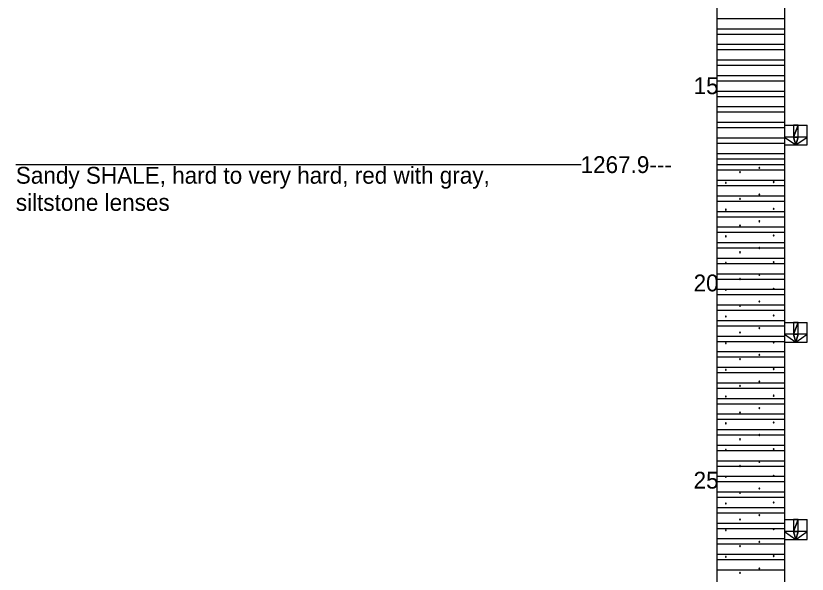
# Model space of a CAD drawing. Extents: x 7 to 126, y 24 to 56.
# Drawn here: x 27.98 to 33.81, y 42.13 to 46.24 of the extents above; entities that cross this region are included whole.
import ezdxf

# ---------------------------------------------------------------- set-up
doc = ezdxf.new("R2010")
doc.units = 0

msp = doc.modelspace()

# ---------------------------------------------------------------- linework, layer by layer
for points in [[(33.1403, 50.0867), (33.1403, 38.1681)], [(33.6403, 50.0867), (33.6403, 38.1681)], [(33.1403, 46.2217), (33.6403, 46.2217)], [(33.1403, 46.1463), (33.6403, 46.1463)], [(33.1403, 46.1069), (33.6403, 46.1069)], [(33.1403, 46.0315), (33.6403, 46.0315)], [(33.1403, 45.9921), (33.6403, 45.9921)], [(33.1403, 45.9166), (33.6403, 45.9166)], [(33.1403, 45.8773), (33.6403, 45.8773)], [(33.1403, 45.8018), (33.6403, 45.8018)], [(33.1403, 45.7624), (33.6403, 45.7624)], [(33.1403, 45.687), (33.6403, 45.687)], [(33.1403, 45.6476), (33.6403, 45.6476)], [(33.1403, 45.5721), (33.6403, 45.5721)], [(33.1403, 45.5328), (33.6403, 45.5328)], [(33.1403, 45.4573), (33.6403, 45.4573)], [(33.6403, 45.4356), (33.807, 45.4356)], [(33.807, 45.2902), (33.807, 45.4356)], [(33.1403, 45.4179), (33.6403, 45.4179)], [(33.1403, 45.3425), (33.6403, 45.3425)], [(33.1403, 45.3031), (33.6403, 45.3031)], [(33.6403, 45.2902), (33.807, 45.2902)], [(33.1403, 45.2277), (33.6403, 45.2277)], [(27.9751, 45.1449), (32.1417, 45.1449)], [(33.1403, 45.1883), (33.6403, 45.1883)], [(33.1403, 45.1449), (33.6403, 45.1449)], [(33.1403, 45.1449), (33.6403, 45.1449)], [(33.1403, 45.1055), (33.6403, 45.1055)], [(33.3154, 45.089), (33.3137, 45.0919), (33.3104, 45.0919), (33.3088, 45.0891), (33.3104, 45.0862), (33.3137, 45.0862), (33.3154, 45.089)], [(33.4579, 45.1209), (33.4563, 45.1237), (33.453, 45.1237), (33.4514, 45.1209), (33.453, 45.1181), (33.4563, 45.1181), (33.4579, 45.1209)], [(33.1403, 45.03), (33.6403, 45.03)], [(33.1403, 44.9907), (33.6403, 44.9907)], [(33.2107, 45.0101), (33.2091, 45.0129), (33.2058, 45.0129), (33.2041, 45.0101), (33.2058, 45.0072), (33.2091, 45.0072), (33.2107, 45.0101)], [(33.5635, 45.0166), (33.5618, 45.0195), (33.5585, 45.0195), (33.5569, 45.0166), (33.5585, 45.0138), (33.5618, 45.0138), (33.5635, 45.0166)], [(33.1403, 44.9152), (33.6403, 44.9152)], [(33.4579, 44.9241), (33.4563, 44.9269), (33.453, 44.9269), (33.4514, 44.9241), (33.453, 44.9212), (33.4563, 44.9212), (33.4579, 44.9241)], [(33.1403, 44.8758), (33.6403, 44.8758)], [(33.3154, 44.8922), (33.3137, 44.8951), (33.3104, 44.8951), (33.3088, 44.8922), (33.3104, 44.8894), (33.3137, 44.8894), (33.3154, 44.8922)], [(33.1403, 44.8004), (33.6403, 44.8004)], [(33.2107, 44.8132), (33.2091, 44.8161), (33.2058, 44.8161), (33.2041, 44.8132), (33.2058, 44.8104), (33.2091, 44.8104), (33.2107, 44.8132)], [(33.5635, 44.8197), (33.5618, 44.8226), (33.5585, 44.8226), (33.5569, 44.8197), (33.5585, 44.8169), (33.5618, 44.8169), (33.5635, 44.8197)], [(33.1403, 44.761), (33.6403, 44.761)], [(33.1403, 44.6856), (33.6403, 44.6856)], [(33.3154, 44.6953), (33.3137, 44.6982), (33.3104, 44.6982), (33.3088, 44.6954), (33.3104, 44.6925), (33.3137, 44.6925), (33.3154, 44.6953)], [(33.4579, 44.7272), (33.4563, 44.73), (33.453, 44.73), (33.4514, 44.7272), (33.453, 44.7244), (33.4563, 44.7244), (33.4579, 44.7272)], [(33.1403, 44.6462), (33.6403, 44.6462)], [(33.2107, 44.6164), (33.2091, 44.6192), (33.2058, 44.6192), (33.2041, 44.6164), (33.2058, 44.6135), (33.2091, 44.6135), (33.2107, 44.6164)], [(33.5635, 44.6229), (33.5618, 44.6258), (33.5585, 44.6258), (33.5569, 44.6229), (33.5585, 44.6201), (33.5618, 44.6201), (33.5635, 44.6229)], [(33.1403, 44.5707), (33.6403, 44.5707)], [(33.1403, 44.5314), (33.6403, 44.5314)], [(33.3154, 44.4985), (33.3137, 44.5014), (33.3104, 44.5014), (33.3088, 44.4985), (33.3104, 44.4957), (33.3137, 44.4957), (33.3154, 44.4985)], [(33.4579, 44.5304), (33.4563, 44.5332), (33.453, 44.5332), (33.4514, 44.5304), (33.453, 44.5275), (33.4563, 44.5275), (33.4579, 44.5304)], [(33.1403, 44.4559), (33.6403, 44.4559)], [(33.1403, 44.4165), (33.6403, 44.4165)], [(33.2107, 44.4195), (33.2091, 44.4224), (33.2058, 44.4224), (33.2041, 44.4195), (33.2058, 44.4167), (33.2091, 44.4167), (33.2107, 44.4195)], [(33.5635, 44.426), (33.5618, 44.4289), (33.5585, 44.4289), (33.5569, 44.426), (33.5585, 44.4232), (33.5618, 44.4232), (33.5635, 44.426)], [(33.1403, 44.3411), (33.6403, 44.3411)], [(33.4579, 44.3335), (33.4563, 44.3363), (33.453, 44.3363), (33.4514, 44.3335), (33.453, 44.3307), (33.4563, 44.3307), (33.4579, 44.3335)], [(33.1403, 44.3017), (33.6403, 44.3017)], [(33.3154, 44.3016), (33.3137, 44.3045), (33.3104, 44.3045), (33.3088, 44.3017), (33.3104, 44.2988), (33.3137, 44.2988), (33.3154, 44.3016)], [(33.1403, 44.2262), (33.6403, 44.2262)], [(33.2107, 44.2227), (33.2091, 44.2255), (33.2058, 44.2255), (33.2041, 44.2227), (33.2058, 44.2198), (33.2091, 44.2198), (33.2107, 44.2227)], [(33.5635, 44.2292), (33.5618, 44.2321), (33.5585, 44.2321), (33.5569, 44.2292), (33.5585, 44.2264), (33.5618, 44.2264), (33.5635, 44.2292)], [(33.1403, 44.1869), (33.6403, 44.1869)], [(33.1403, 44.1114), (33.6403, 44.1114)], [(33.3154, 44.1048), (33.3137, 44.1077), (33.3104, 44.1077), (33.3088, 44.1048), (33.3104, 44.102), (33.3137, 44.102), (33.3154, 44.1048)], [(33.4579, 44.1367), (33.4563, 44.1395), (33.453, 44.1395), (33.4514, 44.1367), (33.453, 44.1338), (33.4563, 44.1338), (33.4579, 44.1367)], [(33.1403, 44.072), (33.6403, 44.072)], [(33.5635, 44.0323), (33.5618, 44.0352), (33.5585, 44.0352), (33.5569, 44.0323), (33.5585, 44.0295), (33.5618, 44.0295), (33.5635, 44.0323)], [(33.1403, 43.9966), (33.6403, 43.9966)], [(33.2107, 44.0258), (33.2091, 44.0287), (33.2058, 44.0287), (33.2041, 44.0258), (33.2058, 44.023), (33.2091, 44.023), (33.2107, 44.0258)], [(33.6403, 43.9821), (33.807, 43.9821)], [(33.807, 43.8367), (33.807, 43.9821)], [(33.1403, 43.9572), (33.6403, 43.9572)], [(33.4579, 43.9398), (33.4563, 43.9426), (33.453, 43.9426), (33.4514, 43.9398), (33.453, 43.937), (33.4563, 43.937), (33.4579, 43.9398)], [(33.1403, 43.8817), (33.6403, 43.8817)], [(33.3154, 43.9079), (33.3137, 43.9108), (33.3104, 43.9108), (33.3088, 43.908), (33.3104, 43.9051), (33.3137, 43.9051), (33.3154, 43.9079)], [(33.1403, 43.8424), (33.6403, 43.8424)], [(33.2107, 43.829), (33.2091, 43.8318), (33.2058, 43.8318), (33.2041, 43.829), (33.2058, 43.8261), (33.2091, 43.8261), (33.2107, 43.829)], [(33.5635, 43.8355), (33.5618, 43.8384), (33.5585, 43.8384), (33.5569, 43.8355), (33.5585, 43.8327), (33.5618, 43.8327), (33.5635, 43.8355)], [(33.6403, 43.8367), (33.807, 43.8367)], [(33.1403, 43.7669), (33.6403, 43.7669)], [(33.4579, 43.743), (33.4563, 43.7458), (33.453, 43.7458), (33.4514, 43.743), (33.453, 43.7401), (33.4563, 43.7401), (33.4579, 43.743)], [(33.1403, 43.7275), (33.6403, 43.7275)], [(33.3154, 43.7111), (33.3137, 43.714), (33.3104, 43.714), (33.3088, 43.7111), (33.3104, 43.7083), (33.3137, 43.7083), (33.3154, 43.7111)], [(33.1403, 43.6521), (33.6403, 43.6521)], [(33.2107, 43.6321), (33.2091, 43.635), (33.2058, 43.635), (33.2041, 43.6321), (33.2058, 43.6293), (33.2091, 43.6293), (33.2107, 43.6321)], [(33.5635, 43.6386), (33.5618, 43.6415), (33.5585, 43.6415), (33.5569, 43.6386), (33.5585, 43.6358), (33.5618, 43.6358), (33.5635, 43.6386)], [(33.1403, 43.6127), (33.6403, 43.6127)], [(33.1403, 43.5373), (33.6403, 43.5373)], [(33.3154, 43.5142), (33.3137, 43.5171), (33.3104, 43.5171), (33.3088, 43.5143), (33.3104, 43.5114), (33.3137, 43.5114), (33.3154, 43.5142)], [(33.4579, 43.5461), (33.4563, 43.5489), (33.453, 43.5489), (33.4514, 43.5461), (33.453, 43.5433), (33.4563, 43.5433), (33.4579, 43.5461)], [(33.1403, 43.4979), (33.6403, 43.4979)], [(33.1403, 43.4224), (33.6403, 43.4224)], [(33.2107, 43.4353), (33.2091, 43.4381), (33.2058, 43.4381), (33.2041, 43.4353), (33.2058, 43.4324), (33.2091, 43.4324), (33.2107, 43.4353)], [(33.5635, 43.4418), (33.5618, 43.4447), (33.5585, 43.4447), (33.5569, 43.4418), (33.5585, 43.439), (33.5618, 43.439), (33.5635, 43.4418)], [(33.1403, 43.3831), (33.6403, 43.3831)], [(33.4579, 43.3493), (33.4563, 43.3521), (33.453, 43.3521), (33.4514, 43.3493), (33.453, 43.3464), (33.4563, 43.3464), (33.4579, 43.3493)], [(33.1403, 43.3076), (33.6403, 43.3076)], [(33.3154, 43.3174), (33.3137, 43.3203), (33.3104, 43.3203), (33.3088, 43.3174), (33.3104, 43.3146), (33.3137, 43.3146), (33.3154, 43.3174)], [(33.1403, 43.2682), (33.6403, 43.2682)], [(33.2107, 43.2384), (33.2091, 43.2413), (33.2058, 43.2413), (33.2041, 43.2384), (33.2058, 43.2356), (33.2091, 43.2356), (33.2107, 43.2384)], [(33.5635, 43.2449), (33.5618, 43.2478), (33.5585, 43.2478), (33.5569, 43.2449), (33.5585, 43.2421), (33.5618, 43.2421), (33.5635, 43.2449)], [(33.1403, 43.1928), (33.6403, 43.1928)], [(33.1403, 43.1534), (33.6403, 43.1534)], [(33.3154, 43.1205), (33.3137, 43.1234), (33.3104, 43.1234), (33.3088, 43.1206), (33.3104, 43.1177), (33.3137, 43.1177), (33.3154, 43.1205)], [(33.4579, 43.1524), (33.4563, 43.1552), (33.453, 43.1552), (33.4514, 43.1524), (33.453, 43.1496), (33.4563, 43.1496), (33.4579, 43.1524)], [(33.1403, 43.0779), (33.6403, 43.0779)], [(33.2107, 43.0416), (33.2091, 43.0444), (33.2058, 43.0444), (33.2041, 43.0416), (33.2058, 43.0387), (33.2091, 43.0387), (33.2107, 43.0416)], [(33.5635, 43.0481), (33.5618, 43.051), (33.5585, 43.051), (33.5569, 43.0481), (33.5585, 43.0453), (33.5618, 43.0453), (33.5635, 43.0481)], [(33.1403, 43.0386), (33.6403, 43.0386)], [(33.1403, 42.9631), (33.6403, 42.9631)], [(33.1403, 42.9237), (33.6403, 42.9237)], [(33.3154, 42.9237), (33.3137, 42.9266), (33.3104, 42.9266), (33.3088, 42.9237), (33.3104, 42.9209), (33.3137, 42.9209), (33.3154, 42.9237)], [(33.4579, 42.9556), (33.4563, 42.9584), (33.453, 42.9584), (33.4514, 42.9556), (33.453, 42.9527), (33.4563, 42.9527), (33.4579, 42.9556)], [(33.1403, 42.8483), (33.6403, 42.8483)], [(33.1403, 42.8089), (33.6403, 42.8089)], [(33.2107, 42.8447), (33.2091, 42.8476), (33.2058, 42.8476), (33.2041, 42.8447), (33.2058, 42.8419), (33.2091, 42.8419), (33.2107, 42.8447)], [(33.5635, 42.8512), (33.5618, 42.8541), (33.5585, 42.8541), (33.5569, 42.8512), (33.5585, 42.8484), (33.5618, 42.8484), (33.5635, 42.8512)], [(33.4579, 42.7587), (33.4563, 42.7615), (33.453, 42.7615), (33.4514, 42.7587), (33.453, 42.7559), (33.4563, 42.7559), (33.4579, 42.7587)], [(33.1403, 42.7335), (33.6403, 42.7335)], [(33.1403, 42.6941), (33.6403, 42.6941)], [(33.3154, 42.7268), (33.3137, 42.7297), (33.3104, 42.7297), (33.3088, 42.7269), (33.3104, 42.724), (33.3137, 42.724), (33.3154, 42.7268)], [(33.2107, 42.6479), (33.2091, 42.6507), (33.2058, 42.6507), (33.2041, 42.6479), (33.2058, 42.645), (33.2091, 42.645), (33.2107, 42.6479)], [(33.5635, 42.6544), (33.5618, 42.6573), (33.5585, 42.6573), (33.5569, 42.6544), (33.5585, 42.6516), (33.5618, 42.6516), (33.5635, 42.6544)], [(33.1403, 42.6186), (33.6403, 42.6186)], [(33.1403, 42.5793), (33.6403, 42.5793)], [(33.3154, 42.53), (33.3137, 42.5329), (33.3104, 42.5329), (33.3088, 42.53), (33.3104, 42.5272), (33.3137, 42.5272), (33.3154, 42.53)], [(33.4579, 42.5619), (33.4563, 42.5647), (33.453, 42.5647), (33.4514, 42.5619), (33.453, 42.559), (33.4563, 42.559), (33.4579, 42.5619)], [(33.6403, 42.5286), (33.807, 42.5286)], [(33.807, 42.3832), (33.807, 42.5286)], [(33.1403, 42.5038), (33.6403, 42.5038)], [(33.1403, 42.4644), (33.6403, 42.4644)], [(33.5635, 42.4575), (33.5618, 42.4604), (33.5585, 42.4604), (33.5569, 42.4575), (33.5585, 42.4547), (33.5618, 42.4547), (33.5635, 42.4575)], [(33.2107, 42.451), (33.2091, 42.4539), (33.2058, 42.4539), (33.2041, 42.451), (33.2058, 42.4482), (33.2091, 42.4482), (33.2107, 42.451)], [(33.1403, 42.389), (33.6403, 42.389)], [(33.1403, 42.3496), (33.6403, 42.3496)], [(33.4579, 42.365), (33.4563, 42.3678), (33.453, 42.3678), (33.4514, 42.365), (33.453, 42.3622), (33.4563, 42.3622), (33.4579, 42.365)], [(33.6403, 42.3832), (33.807, 42.3832)], [(33.3154, 42.3331), (33.3137, 42.336), (33.3104, 42.336), (33.3088, 42.3332), (33.3104, 42.3303), (33.3137, 42.3303), (33.3154, 42.3331)], [(33.1403, 42.2741), (33.6403, 42.2741)], [(33.1403, 42.2348), (33.6403, 42.2348)], [(33.2107, 42.2542), (33.2091, 42.257), (33.2058, 42.257), (33.2041, 42.2542), (33.2058, 42.2513), (33.2091, 42.2513), (33.2107, 42.2542)], [(33.5635, 42.2607), (33.5618, 42.2636), (33.5585, 42.2636), (33.5569, 42.2607), (33.5585, 42.2579), (33.5618, 42.2579), (33.5635, 42.2607)], [(33.4579, 42.1682), (33.4563, 42.171), (33.453, 42.171), (33.4514, 42.1682), (33.453, 42.1653), (33.4563, 42.1653), (33.4579, 42.1682)], [(33.1403, 42.1593), (33.6403, 42.1593)], [(33.3154, 42.1363), (33.3137, 42.1392), (33.3104, 42.1392), (33.3088, 42.1363), (33.3104, 42.1335), (33.3137, 42.1335), (33.3154, 42.1363)]]:
    msp.add_lwpolyline(points)
for points in [[(33.707, 45.3484), (33.7403, 45.3484), (33.7403, 45.4356), (33.707, 45.3484)], [(33.707, 45.3484), (33.7403, 45.4356), (33.707, 45.4356), (33.707, 45.3484)], [(33.707, 45.3484), (33.6403, 45.3484), (33.7236, 45.2902), (33.707, 45.3484)], [(33.707, 45.3484), (33.7236, 45.2902), (33.7403, 45.3484), (33.707, 45.3484)], [(33.7236, 45.2902), (33.807, 45.3484), (33.7403, 45.3484), (33.7236, 45.2902)], [(33.707, 43.8949), (33.7403, 43.8949), (33.7403, 43.9821), (33.707, 43.8949)], [(33.707, 43.8949), (33.7403, 43.9821), (33.707, 43.9821), (33.707, 43.8949)], [(33.707, 43.8949), (33.6403, 43.8949), (33.7236, 43.8367), (33.707, 43.8949)], [(33.707, 43.8949), (33.7236, 43.8367), (33.7403, 43.8949), (33.707, 43.8949)], [(33.7236, 43.8367), (33.807, 43.8949), (33.7403, 43.8949), (33.7236, 43.8367)], [(33.707, 42.4414), (33.7403, 42.4414), (33.7403, 42.5286), (33.707, 42.4414)], [(33.707, 42.4414), (33.7403, 42.5286), (33.707, 42.5286), (33.707, 42.4414)], [(33.707, 42.4414), (33.6403, 42.4414), (33.7236, 42.3832), (33.707, 42.4414)], [(33.707, 42.4414), (33.7236, 42.3832), (33.7403, 42.4414), (33.707, 42.4414)], [(33.7236, 42.3832), (33.807, 42.4414), (33.7403, 42.4414), (33.7236, 42.3832)]]:
    msp.add_lwpolyline(points, close=True)

# ---------------------------------------------------------------- texts
for s, p in [('15', (32.9699, 45.6643)), ('1267.9---', (32.1368, 45.0829)), ('Sandy SHALE, hard to very hard, red with gray,', (27.9751, 45.0042)), ('siltstone lenses', (27.9751, 44.8042)), ('20', (32.9699, 44.2108)), ('25', (32.9699, 42.7573))]:
    msp.add_text(s, height=0.124).set_placement(p)

doc.saveas('drawing.dxf')
